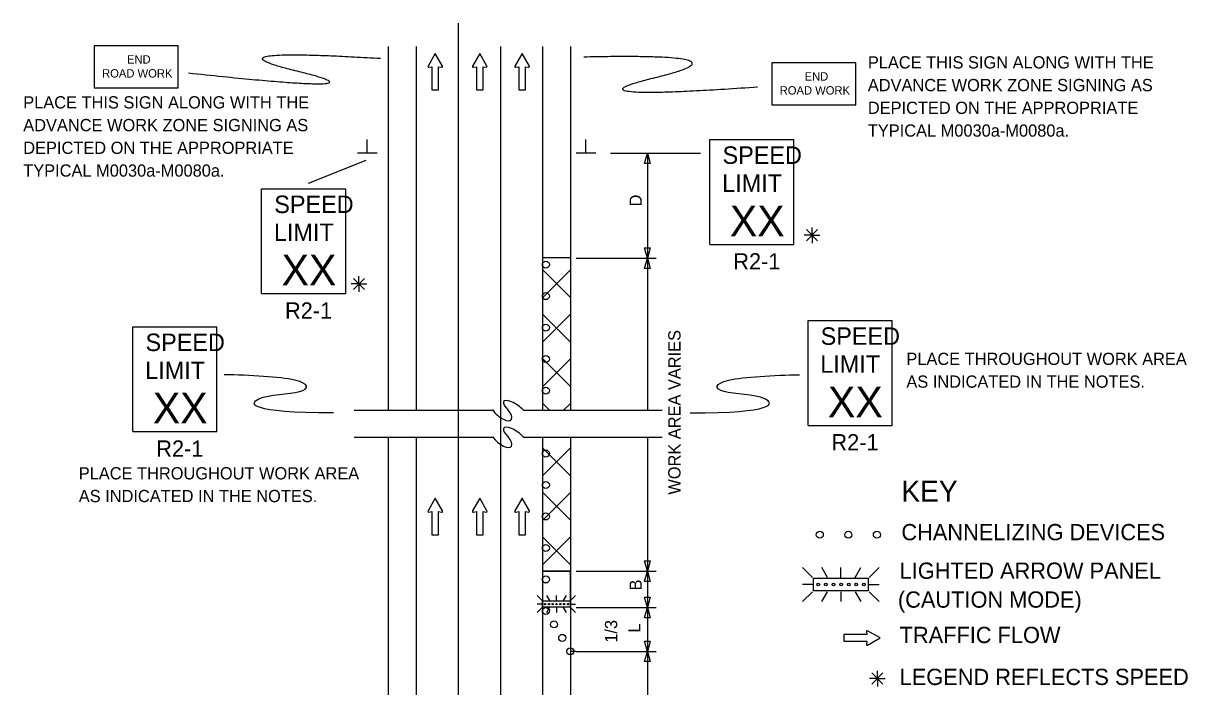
# Model space of a CAD drawing. Extents: x 16737 to 18479, y 6975 to 8225.
# Drawn here: x 16737 to 17402, y 7846 to 8225 of the extents above; entities that cross this region are included whole.
import ezdxf

# ---------------------------------------------------------------- set-up
doc = ezdxf.new("R2010")
doc.units = 0
for name, color, linetype in [('ALI_LEGAL_EX', 7, 'Continuous'), ('MT_SCRATCH_LEVEL_A', 7, 'Continuous'), ('MT_SCRATCH_LEVEL_E', 7, 'Continuous'), ('PAVT_EDGE_EX', 7, 'Continuous'), ('TRAFFIC_SIGNS_PR', 7, 'Continuous'), ('TYPICAL_EX', 7, 'Continuous'), ('TYPICAL_TEXT_DIMEN_EX', 7, 'Continuous'), ('TYPICAL_TEXT_DIMEN_PR', 7, 'Continuous')]:
    doc.layers.add(name, color=color, linetype=linetype)

msp = doc.modelspace()

# ---------------------------------------------------------------- linework, layer by layer
at = {"layer": 'ALI_LEGAL_EX'}
for points in [[(16985.65, 8225.29), (16985.65, 8200.29)], [(16985.65, 8216), (16985.65, 8191)], [(16985.65, 8211.96), (16985.65, 8200.29)], [(17009.65, 8211.96), (17009.65, 8200.29)], [(16985.65, 8125.29), (16985.65, 8100.29)], [(16985.65, 8125.29), (16985.65, 8100.29)], [(17009.65, 8125.29), (17009.65, 8100.29)], [(16985.65, 8025.29), (16985.65, 8004.01)], [(17009.65, 8025.29), (17009.65, 8000.29)], [(16985.65, 7961.57), (16985.65, 7936.57)], [(16985.65, 7925.29), (16985.65, 7900.29)], [(17009.65, 7925.29), (17009.65, 7900.29)]]:
    msp.add_lwpolyline(points, dxfattribs=at)
at = {"layer": 'MT_SCRATCH_LEVEL_A'}
for p, q in [((17049.65, 8068.41), (17033.65, 8084.41)), ((17033.65, 8068.3), (17049.65, 8084.3)), ((17049.65, 8042.96), (17033.65, 8058.96)), ((17033.65, 8042.85), (17049.65, 8058.85)), ((17049.65, 8017.5), (17033.65, 8033.5)), ((17033.65, 8017.39), (17049.65, 8033.39)), ((17037.68, 8004.02), (17033.65, 8008.05)), ((17045.64, 8003.92), (17049.65, 8007.94)), ((17049.65, 7966.59), (17033.65, 7982.59)), ((17033.65, 7966.48), (17049.65, 7982.48)), ((17049.65, 7941.13), (17033.65, 7957.13)), ((17033.65, 7941.02), (17049.65, 7957.02)), ((17049.65, 7915.68), (17033.65, 7931.68)), ((17033.65, 7915.57), (17049.65, 7931.57))]:
    msp.add_line(p, q, dxfattribs=at)
at = {"layer": 'MT_SCRATCH_LEVEL_E'}
for p, q in [((16972.46, 8208.07), (16968.34, 8200.83)), ((16972.46, 8208.07), (16968.34, 8200.83)), ((16976.6, 8200.83), (16972.46, 8208.07)), ((16976.6, 8200.83), (16972.46, 8208.07)), ((16997.88, 8208.07), (16993.77, 8200.83)), ((16997.88, 8208.07), (16993.77, 8200.83)), ((17002.03, 8200.83), (16997.88, 8208.07)), ((17002.03, 8200.83), (16997.88, 8208.07)), ((17022.09, 8208.07), (17017.98, 8200.83)), ((17022.09, 8208.07), (17017.98, 8200.83)), ((17026.24, 8200.83), (17022.09, 8208.07)), ((17026.24, 8200.83), (17022.09, 8208.07)), ((16968.83, 8200.14), (16970.6, 8200.46)), ((16968.83, 8200.14), (16970.6, 8200.46)), ((16970.6, 8200.46), (16970.6, 8187.2)), ((16970.6, 8200.46), (16970.6, 8187.2)), ((16974.35, 8187.2), (16974.35, 8200.46)), ((16974.35, 8200.46), (16976.12, 8200.14)), ((16974.35, 8187.2), (16974.35, 8200.46)), ((16974.35, 8200.46), (16976.12, 8200.14)), ((16994.25, 8200.14), (16996.03, 8200.46)), ((16994.25, 8200.14), (16996.03, 8200.46)), ((16996.03, 8200.46), (16996.03, 8187.2)), ((16996.03, 8200.46), (16996.03, 8187.2)), ((16999.77, 8187.2), (16999.77, 8200.46)), ((16999.77, 8200.46), (17001.55, 8200.14)), ((16999.77, 8187.2), (16999.77, 8200.46)), ((16999.77, 8200.46), (17001.55, 8200.14)), ((17018.47, 8200.14), (17020.24, 8200.46)), ((17018.47, 8200.14), (17020.24, 8200.46)), ((17020.24, 8200.46), (17020.24, 8187.2)), ((17020.24, 8200.46), (17020.24, 8187.2)), ((17023.98, 8187.2), (17023.98, 8200.46)), ((17023.98, 8200.46), (17025.76, 8200.14)), ((17023.98, 8187.2), (17023.98, 8200.46)), ((17023.98, 8200.46), (17025.76, 8200.14)), ((16970.6, 8187.2), (16974.35, 8187.2)), ((16970.6, 8187.2), (16974.35, 8187.2)), ((16996.03, 8187.2), (16999.77, 8187.2)), ((16996.03, 8187.2), (16999.77, 8187.2)), ((17020.24, 8187.2), (17023.98, 8187.2)), ((17020.24, 8187.2), (17023.98, 8187.2)), ((16972.46, 7953.64), (16968.34, 7946.4)), ((16972.46, 7953.64), (16968.34, 7946.4)), ((16976.6, 7946.4), (16972.46, 7953.64)), ((16976.6, 7946.4), (16972.46, 7953.64)), ((16997.88, 7953.64), (16993.77, 7946.4)), ((16997.88, 7953.64), (16993.77, 7946.4)), ((17002.03, 7946.4), (16997.88, 7953.64)), ((17002.03, 7946.4), (16997.88, 7953.64)), ((17022.09, 7953.64), (17017.98, 7946.4)), ((17022.09, 7953.64), (17017.98, 7946.4)), ((17026.24, 7946.4), (17022.09, 7953.64)), ((17026.24, 7946.4), (17022.09, 7953.64)), ((16968.83, 7945.72), (16970.6, 7946.03)), ((16968.83, 7945.72), (16970.6, 7946.03)), ((16970.6, 7946.03), (16970.6, 7932.78)), ((16970.6, 7946.03), (16970.6, 7932.78)), ((16974.35, 7932.78), (16974.35, 7946.03)), ((16974.35, 7946.03), (16976.12, 7945.72)), ((16974.35, 7932.78), (16974.35, 7946.03)), ((16974.35, 7946.03), (16976.12, 7945.72)), ((16994.25, 7945.72), (16996.03, 7946.03)), ((16994.25, 7945.72), (16996.03, 7946.03)), ((16996.03, 7946.03), (16996.03, 7932.78)), ((16996.03, 7946.03), (16996.03, 7932.78)), ((16999.77, 7932.78), (16999.77, 7946.03)), ((16999.77, 7946.03), (17001.55, 7945.72)), ((16999.77, 7932.78), (16999.77, 7946.03)), ((16999.77, 7946.03), (17001.55, 7945.72)), ((17018.47, 7945.72), (17020.24, 7946.03)), ((17018.47, 7945.72), (17020.24, 7946.03)), ((17020.24, 7946.03), (17020.24, 7932.78)), ((17020.24, 7946.03), (17020.24, 7932.78)), ((17023.98, 7932.78), (17023.98, 7946.03)), ((17023.98, 7946.03), (17025.76, 7945.72)), ((17023.98, 7932.78), (17023.98, 7946.03)), ((17023.98, 7946.03), (17025.76, 7945.72)), ((16970.6, 7932.78), (16974.35, 7932.78)), ((16970.6, 7932.78), (16974.35, 7932.78)), ((16996.03, 7932.78), (16999.77, 7932.78)), ((16996.03, 7932.78), (16999.77, 7932.78)), ((17020.24, 7932.78), (17023.98, 7932.78)), ((17020.24, 7932.78), (17023.98, 7932.78)), ((17218.8, 7877.48), (17219.11, 7875.7)), ((17218.8, 7877.48), (17219.11, 7875.7)), ((17226.72, 7873.85), (17219.48, 7877.96)), ((17226.72, 7873.85), (17219.48, 7877.96)), ((17219.11, 7875.7), (17205.86, 7875.7)), ((17205.86, 7875.7), (17205.86, 7871.96)), ((17219.11, 7875.7), (17205.86, 7875.7)), ((17205.86, 7875.7), (17205.86, 7871.96)), ((17205.86, 7871.96), (17219.11, 7871.96)), ((17205.86, 7871.96), (17219.11, 7871.96)), ((17219.11, 7871.96), (17218.8, 7870.18)), ((17219.11, 7871.96), (17218.8, 7870.18)), ((17219.48, 7869.7), (17226.72, 7873.85)), ((17219.48, 7869.7), (17226.72, 7873.85))]:
    msp.add_line(p, q, dxfattribs=at)
for centre, start, end in [((16968.75, 8200.6), 150.42484, 279.96381), ((16968.75, 8200.6), 150.42484, 279.96381), ((16976.19, 8200.6), 260.03619, 29.77312), ((16976.19, 8200.6), 260.03619, 29.77312), ((16994.18, 8200.6), 150.42484, 279.96381), ((16994.18, 8200.6), 150.42484, 279.96381), ((17001.62, 8200.6), 260.03619, 29.77312), ((17001.62, 8200.6), 260.03619, 29.77312), ((17018.39, 8200.6), 150.42484, 279.96381), ((17018.39, 8200.6), 150.42484, 279.96381), ((17025.83, 8200.6), 260.03619, 29.77312), ((17025.83, 8200.6), 260.03619, 29.77312), ((16968.75, 7946.18), 150.42484, 279.96381), ((16968.75, 7946.18), 150.42484, 279.96381), ((16976.19, 7946.18), 260.03619, 29.77312), ((16976.19, 7946.18), 260.03619, 29.77312), ((16994.18, 7946.18), 150.42484, 279.96381), ((16994.18, 7946.18), 150.42484, 279.96381), ((17001.62, 7946.18), 260.03619, 29.77312), ((17001.62, 7946.18), 260.03619, 29.77312), ((17018.39, 7946.18), 150.42484, 279.96381), ((17018.39, 7946.18), 150.42484, 279.96381), ((17025.83, 7946.18), 260.03619, 29.77312), ((17025.83, 7946.18), 260.03619, 29.77312), ((17219.26, 7877.55), 60.42484, 189.96381), ((17219.26, 7877.55), 60.42484, 189.96381), ((17219.26, 7870.11), 170.03619, 299.77312), ((17219.26, 7870.11), 170.03619, 299.77312)]:
    msp.add_arc(centre, 0.463, start, end, dxfattribs=at)
at = {"layer": 'PAVT_EDGE_EX'}
for p, q in [((16945.65, 8211.96), (16945.65, 8004.01)), ((16961.65, 8211.96), (16961.65, 8004.01)), ((16985.65, 8211.96), (16985.65, 7344.79)), ((17009.65, 8211.96), (17009.65, 7344.79)), ((17033.65, 8211.96), (17033.65, 8004.01)), ((17049.65, 8211.96), (17049.65, 8004.01)), ((16985.65, 8097.28), (16985.65, 7344.79)), ((17009.65, 8097.28), (17009.65, 7344.79)), ((17033.65, 8091.4), (17049.65, 8091.4)), ((17035.65, 8015.25), (17035.65, 8015.25)), ((16945.65, 7988.69), (16945.65, 7942.5)), ((16961.65, 7988.57), (16961.65, 7942.41)), ((17033.65, 7988.69), (17033.65, 7942.16)), ((17049.65, 7988.69), (17049.65, 7942.41)), ((16945.65, 7942.5), (16945.65, 7344.79)), ((16961.65, 7942.41), (16961.65, 7344.79)), ((17033.65, 7942.16), (17033.65, 7344.79)), ((17049.65, 7942.41), (17049.65, 7344.79)), ((17033.65, 7911.96), (17049.65, 7911.96)), ((17049.65, 7911.96), (17033.65, 7911.96)), ((17033.65, 7911.96), (17033.65, 7894.97)), ((17049.65, 7894.97), (17049.65, 7911.96)), ((17033.65, 7894.97), (17049.65, 7894.97)), ((17033.65, 7894.97), (17049.65, 7894.97)), ((17052.95, 7866.13), (17049.65, 7866.13))]:
    msp.add_line(p, q, dxfattribs=at)
at = {"layer": 'TRAFFIC_SIGNS_PR'}
for p, q in [((17129.39, 8158.81), (17177.39, 8158.81)), ((17129.39, 8098.81), (17129.39, 8158.81)), ((17177.39, 8098.81), (17177.39, 8158.81)), ((16873.29, 8130.68), (16921.29, 8130.68)), ((16873.29, 8070.68), (16873.29, 8130.68)), ((16921.29, 8070.68), (16921.29, 8130.68)), ((17129.39, 8098.81), (17177.39, 8098.81)), ((16873.29, 8070.68), (16921.29, 8070.68)), ((16799.74, 8051.76), (16847.74, 8051.76)), ((16799.74, 7991.76), (16799.74, 8051.76)), ((16847.74, 7991.76), (16847.74, 8051.76)), ((17185.44, 8055.33), (17233.44, 8055.33)), ((17185.44, 7995.33), (17185.44, 8055.33)), ((17233.44, 7995.33), (17233.44, 8055.33)), ((16799.74, 7991.76), (16847.74, 7991.76)), ((17185.44, 7995.33), (17233.44, 7995.33)), ((17182.37, 7914.01), (17188.01, 7908.37)), ((17196.54, 7908.37), (17193.29, 7914.01)), ((17204.18, 7908.37), (17204.18, 7914.01)), ((17212.45, 7908.37), (17215.7, 7914.01)), ((17220.35, 7908.37), (17225.99, 7914.01)), ((17188.01, 7904.31), (17182.37, 7904.31)), ((17191.28, 7904.31), (17191.28, 7904.31)), ((17195.63, 7904.31), (17195.63, 7904.31)), ((17199.98, 7904.31), (17199.98, 7904.31)), ((17204.33, 7904.31), (17204.33, 7904.31)), ((17208.67, 7904.31), (17208.67, 7904.31)), ((17213.02, 7904.31), (17213.02, 7904.31)), ((17217.36, 7904.31), (17217.36, 7904.31)), ((17220.35, 7904.31), (17225.99, 7904.31)), ((17030.76, 7898.01), (17033.58, 7895.19)), ((17037.85, 7895.19), (17036.22, 7898.01)), ((17041.67, 7895.19), (17041.67, 7898.01)), ((17045.8, 7895.19), (17047.43, 7898.01)), ((17049.75, 7895.19), (17052.57, 7898.01)), ((17182.37, 7894.61), (17188.01, 7900.24)), ((17193.24, 7894.6), (17196.49, 7900.24)), ((17204.18, 7900.24), (17204.18, 7894.6)), ((17215.75, 7894.6), (17212.5, 7900.24)), ((17220.35, 7900.24), (17225.99, 7894.6)), ((17033.58, 7893.16), (17030.76, 7893.16)), ((17030.76, 7888.31), (17033.58, 7891.13)), ((17035.22, 7893.16), (17035.22, 7893.16)), ((17036.2, 7888.31), (17037.83, 7891.13)), ((17037.4, 7893.16), (17037.4, 7893.16)), ((17039.57, 7893.16), (17039.57, 7893.16)), ((17041.67, 7891.13), (17041.67, 7888.31)), ((17041.74, 7893.16), (17041.74, 7893.16)), ((17043.92, 7893.16), (17043.92, 7893.16)), ((17047.46, 7888.31), (17045.83, 7891.13)), ((17046.09, 7893.16), (17046.09, 7893.16)), ((17048.26, 7893.16), (17048.26, 7893.16)), ((17049.75, 7893.16), (17052.57, 7893.16)), ((17049.75, 7891.13), (17052.57, 7888.31))]:
    msp.add_line(p, q, dxfattribs=at)
for points in [[(16777.61, 8188.32), (16825.61, 8188.32), (16825.61, 8212.32), (16777.61, 8212.32)], [(17164.73, 8178.59), (17212.73, 8178.59), (17212.73, 8202.59), (17164.73, 8202.59)], [(17219.88, 7900.71), (17188.47, 7900.71), (17188.47, 7907.91), (17219.88, 7907.91)], [(17049.52, 7891.36), (17033.81, 7891.36), (17033.81, 7894.96), (17049.52, 7894.96)]]:
    msp.add_lwpolyline(points, close=True, dxfattribs=at)
for centre, radius in [((17035.65, 8087.25), 2), ((17035.65, 8069.25), 2), ((17035.65, 8051.25), 2), ((17035.65, 8033.25), 2), ((17035.65, 8015.25), 2), ((17035.65, 7979.25), 2), ((17035.65, 7961.25), 2), ((17035.65, 7943.25), 2), ((17192.17, 7932.83), 2), ((17208.47, 7932.83), 2), ((17224.77, 7932.83), 2), ((17035.65, 7925.25), 2), ((17035.65, 7907.25), 2), ((17191.32, 7904.31), 0.758), ((17195.63, 7904.31), 0.758), ((17199.98, 7904.31), 0.758), ((17204.32, 7904.31), 0.758), ((17208.67, 7904.31), 0.758), ((17213.02, 7904.31), 0.758), ((17217.37, 7904.31), 0.758), ((17035.65, 7889.25), 2), ((17035.7, 7889.25), 2), ((17035.24, 7893.16), 0.379), ((17037.39, 7893.16), 0.379), ((17039.57, 7893.16), 0.379), ((17041.74, 7893.16), 0.379), ((17043.91, 7893.16), 0.379), ((17046.09, 7893.16), 0.379), ((17048.26, 7893.16), 0.379), ((17040.35, 7881.55), 2), ((17044.99, 7873.84), 2), ((17049.65, 7866.13), 2)]:
    msp.add_circle(centre, radius, dxfattribs=at)
for points in [[(16831.42, 8196.9), (16950.78, 8184.01), (16836.87, 8211.59), (16941.12, 8205.24)], [(17156.66, 8188.77), (17041.44, 8180.53), (17155.34, 8208.11), (17057.4, 8205.95)]]:
    msp.add_open_spline(points, degree=2, dxfattribs=at)
at = {"layer": 'TYPICAL_EX'}
for p, q in [((16926.17, 8004.01), (17005.48, 8004.01)), ((17022.9, 8004.01), (17102.17, 8004.01)), ((16926.17, 7988.69), (17005.48, 7988.69)), ((17022.9, 7988.69), (17102.17, 7988.69))]:
    msp.add_line(p, q, dxfattribs=at)
for centre, major_axis, ratio, start_param, end_param in [((17018.27, 8004.28), (6.66, -4.85), 0.346236, 1.077134, 4.299707), ((17010.23, 8003.47), (-5.67, 4.94), 0.423114, 0.994299, 4.377734), ((17018.27, 7988.96), (6.66, -4.85), 0.346236, 1.077134, 4.299707), ((17010.23, 7988.15), (-5.67, 4.94), 0.423114, 0.994299, 4.377734)]:
    msp.add_ellipse(centre, major_axis=major_axis, ratio=ratio, start_param=start_param, end_param=end_param, dxfattribs=at)
at = {"layer": 'TYPICAL_TEXT_DIMEN_PR'}
for p, q in [((16933.63, 8151), (16933.63, 8158.78)), ((17058.58, 8151), (17058.58, 8158.78)), ((16939.26, 8151), (16928.01, 8151)), ((17064.21, 8151), (17052.96, 8151)), ((17072.65, 8151), (17124.05, 8151)), ((17092.08, 8145.14), (17093.65, 8151)), ((17093.65, 8151), (17093.65, 8091)), ((17093.65, 8151), (17095.22, 8145.14)), ((16900.13, 8133.82), (16932.91, 8147.02)), ((17093.65, 8145.14), (17092.08, 8145.14)), ((17095.22, 8145.14), (17093.65, 8145.14)), ((17187.71, 8104.13), (17183.18, 8104.13)), ((17184.53, 8107.32), (17190.9, 8100.94)), ((17190.9, 8107.32), (17184.53, 8100.94)), ((17187.71, 8104.13), (17187.71, 8108.58)), ((17187.71, 8104.13), (17190.9, 8104.13)), ((17187.71, 8104.13), (17192.19, 8104.13)), ((17187.71, 8104.13), (17187.71, 8099.63)), ((17093.65, 8091), (17092.08, 8096.86)), ((17092.08, 8096.86), (17093.65, 8096.86)), ((17093.65, 8096.86), (17095.22, 8096.86)), ((17095.22, 8096.86), (17093.65, 8091)), ((17052.95, 8091), (17098.65, 8091)), ((17092.08, 8085.14), (17093.65, 8091)), ((17093.65, 8091), (17095.22, 8085.14)), ((17093.65, 8091), (17093.65, 8003.81)), ((17093.65, 8085.14), (17092.08, 8085.14)), ((17095.22, 8085.14), (17093.65, 8085.14)), ((16928.88, 8076.2), (16924.35, 8076.2)), ((16925.7, 8079.39), (16932.07, 8073.01)), ((16932.07, 8079.39), (16925.7, 8073.01)), ((16928.88, 8076.2), (16928.88, 8080.66)), ((16928.88, 8076.2), (16932.07, 8076.2)), ((16928.88, 8076.2), (16933.36, 8076.2)), ((16928.88, 8076.2), (16928.88, 8071.7)), ((17093.65, 7988.65), (17093.65, 7911.96)), ((17093.65, 7911.96), (17092.08, 7917.82)), ((17092.08, 7917.82), (17093.65, 7917.82)), ((17093.65, 7917.82), (17095.22, 7917.82)), ((17095.22, 7917.82), (17093.65, 7911.96)), ((17052.95, 7911.96), (17098.65, 7911.96)), ((17092.08, 7906.1), (17093.65, 7911.96)), ((17093.65, 7911.96), (17093.65, 7891.25)), ((17093.65, 7911.96), (17095.22, 7906.1)), ((17093.65, 7906.1), (17092.08, 7906.1)), ((17095.22, 7906.1), (17093.65, 7906.1)), ((17093.65, 7891.25), (17092.08, 7897.11)), ((17092.08, 7897.11), (17093.65, 7897.11)), ((17093.65, 7897.11), (17095.22, 7897.11)), ((17095.22, 7897.11), (17093.65, 7891.25)), ((17052.95, 7891.25), (17098.65, 7891.25)), ((17092.08, 7885.39), (17093.65, 7891.25)), ((17093.65, 7891.25), (17093.65, 7866.13)), ((17093.65, 7891.25), (17095.22, 7885.39)), ((17093.65, 7885.39), (17092.08, 7885.39)), ((17095.22, 7885.39), (17093.65, 7885.39)), ((17093.65, 7866.13), (17092.08, 7871.99)), ((17092.08, 7871.99), (17093.65, 7871.99)), ((17093.65, 7871.99), (17095.22, 7871.99)), ((17095.22, 7871.99), (17093.65, 7866.13)), ((17052.95, 7866.13), (17098.65, 7866.13)), ((17092.08, 7860.27), (17093.65, 7866.13)), ((17093.65, 7866.13), (17093.65, 7806.13)), ((17093.65, 7866.13), (17095.22, 7860.27)), ((17093.65, 7860.27), (17092.08, 7860.27)), ((17095.22, 7860.27), (17093.65, 7860.27)), ((17225.05, 7850.6), (17220.52, 7850.6)), ((17221.86, 7853.78), (17228.24, 7847.41)), ((17228.24, 7853.78), (17221.86, 7847.41)), ((17225.05, 7850.6), (17225.05, 7855.05)), ((17225.05, 7850.6), (17228.24, 7850.6)), ((17225.05, 7850.6), (17229.53, 7850.6)), ((17225.05, 7850.6), (17225.05, 7846.1))]:
    msp.add_line(p, q, dxfattribs=at)
for points in [[(16914.33, 8002.47), (16865.87, 8002.47), (16865.87, 8013.22), (16900.78, 8013.22), (16900.78, 8022.27), (16866.58, 8024.04), (16851.85, 8024.33)], [(17118.1, 8002.47), (17166.57, 8002.47), (17166.57, 8013.22), (17131.65, 8013.22), (17131.65, 8022.27), (17165.86, 8024.04), (17180.59, 8024.33)]]:
    msp.add_open_spline(points, degree=3, dxfattribs=at)

# ---------------------------------------------------------------- texts
at = {"layer": 'TRAFFIC_SIGNS_PR'}
for s, height, p in [('END', 4.789, (16796.36, 8202.23)), ('PLACE THIS SIGN ALONG WITH THE', 7, (17219.61, 8199.44)), ('ROAD WORK', 4.789, (16782.12, 8194.25)), ('END', 4.789, (17183.48, 8192.5)), ('ROAD WORK', 4.789, (17169.24, 8184.52)), ('ADVANCE WORK ZONE SIGNING AS', 7, (17219.61, 8186.44)), ('PLACE THIS SIGN ALONG WITH THE', 7, (16737.09, 8176.57)), ('DEPICTED ON THE APPROPRIATE', 7, (17219.61, 8173.44)), ('ADVANCE WORK ZONE SIGNING AS', 7, (16737.09, 8163.57)), ('TYPICAL M0030a-M0080a.', 7, (17219.61, 8160.44)), ('DEPICTED ON THE APPROPRIATE', 7, (16737.09, 8150.57)), ('SPEED', 10, (17136.6, 8144.89)), ('TYPICAL M0030a-M0080a.', 7, (16737.09, 8137.57)), ('LIMIT', 10, (17136.4, 8128.89)), ('SPEED', 10, (16880.5, 8116.76)), ('XX', 17.538, (17140.78, 8103.51)), ('LIMIT', 10, (16880.3, 8100.76)), ('XX', 17.538, (16884.68, 8075.38)), ('R2-1', 9.3, (17142.74, 8084.51)), ('R2-1', 9.3, (16886.64, 8056.38)), ('SPEED', 10, (17192.65, 8041.41)), ('SPEED', 10, (16806.95, 8037.84)), ('PLACE THROUGHOUT WORK AREA', 7, (17241.64, 8029.89)), ('LIMIT', 10, (16806.74, 8021.84)), ('LIMIT', 10, (17192.45, 8025.41)), ('AS INDICATED IN THE NOTES.', 7, (17241.64, 8016.89)), ('XX', 17.538, (17196.83, 8000.03)), ('XX', 17.538, (16811.13, 7996.46)), ('R2-1', 9.3, (17198.79, 7981.04)), ('R2-1', 9.3, (16813.08, 7977.46)), ('PLACE THROUGHOUT WORK AREA', 7, (16768.81, 7964.45)), ('AS INDICATED IN THE NOTES.', 7, (16768.81, 7951.45))]:
    msp.add_text(s, height=height, dxfattribs=at).set_placement(p)
at = {"layer": 'TYPICAL_TEXT_DIMEN_EX'}
for s, height, p in [('KEY', 12, (17238.79, 7951.71)), ('CHANNELIZING DEVICES', 9.3, (17238.79, 7929.66)), ('LIGHTED ARROW PANEL', 9.3, (17237.79, 7907.61)), ('(CAUTION MODE)', 9.3, (17236.8, 7891.11)), ('TRAFFIC FLOW', 9.3, (17237.79, 7870.86)), ('LEGEND REFLECTS SPEED', 9.3, (17237.78, 7846.88))]:
    msp.add_text(s, height=height, dxfattribs=at).set_placement(p)
at = {"layer": 'TYPICAL_TEXT_DIMEN_PR'}
for s, p in [('D', (17090.46, 8120.54)), ('WORK AREA VARIES', (17112.58, 7955.74)), ('B', (17090.46, 7900.95)), ('1/3', (17076.41, 7871.08)), ('L', (17089.71, 7876.87))]:
    msp.add_text(s, height=7, rotation=90, dxfattribs=at).set_placement(p)

doc.saveas('drawing.dxf')
